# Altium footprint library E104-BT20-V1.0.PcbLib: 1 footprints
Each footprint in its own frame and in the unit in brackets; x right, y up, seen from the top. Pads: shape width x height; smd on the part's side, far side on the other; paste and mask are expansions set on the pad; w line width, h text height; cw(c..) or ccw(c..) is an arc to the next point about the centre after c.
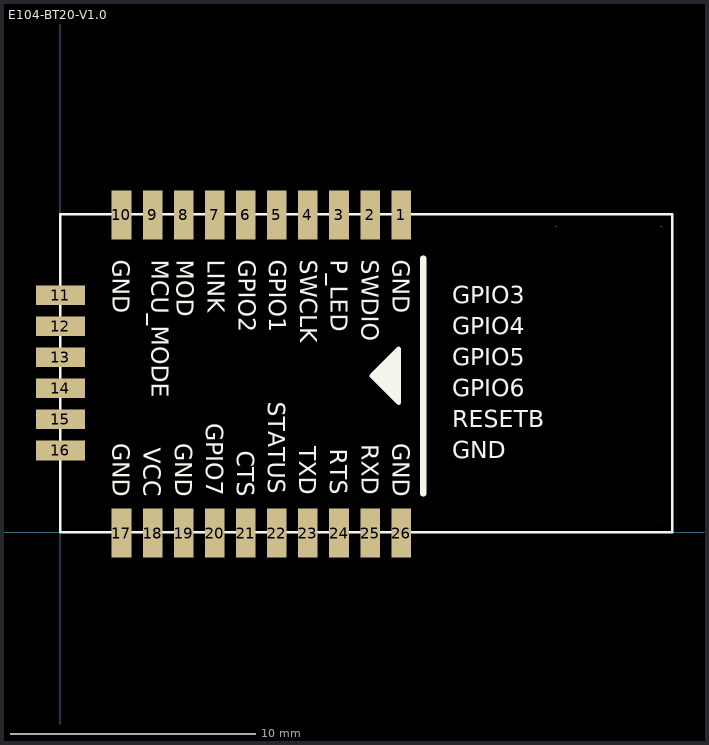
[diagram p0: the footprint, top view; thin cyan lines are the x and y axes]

## E104-BT20-V1.0 [mm]
pads (26):
  rect 0.8x2 smd: 1(13.927,12.975) 2(12.657,12.975) 3(11.387,12.975) 4(10.117,12.975) 5(8.847,12.975) 6(7.577,12.975) 7(6.307,12.975) 8(5.037,12.975) 9(3.77,12.975) 10(2.5,12.975) 17(2.5,-0.025) 18(3.77,-0.025) 19(5.037,-0.025) 20(6.307,-0.025) 21(7.577,-0.025) 22(8.847,-0.025) 23(10.117,-0.025) 24(11.387,-0.025) 25(12.657,-0.025) 26(13.927,-0.025)
  rect 2x0.8 smd: 11(0,9.7) 12(0,8.43) 13(0,7.16) 14(0,5.89) 15(0,4.62) 16(0,3.35)
Top Overlay:
  lines w0.1: 0,0 0,13 25,13 25,0 0,0
  lines w0.2: 13.727,7.2 13.327,6.8 ; 13.327,6.8 13.327,6.4 12.827,6.4 13.127,6.1 13.227,6.1 13.227,6.8 13.327,6.8 ; 13.327,6.8 13.427,6.9 13.427,6.1 13.527,6 13.527,5.8 13.527,7.1 13.627,7.2 13.627,5.7 13.827,5.5 ; 13.827,5.5 13.827,5.3 13.627,5.5 12.727,6.4 13.827,7.5 ; 13.827,5.5 13.827,7.5 ; 13.827,5.5 13.027,6.3 13.027,6.7 13.827,7.5
  lines w0.25: 14.827,1.6 14.827,11.2
  text "GND" at 16.013,3.03 h0.7
  text "RESETB" at 16.013,4.296 h0.7
  text "GPIO5" at 16.013,6.828 h0.7
  text "GPIO3" at 16.013,9.36 h0.7
  text "GPIO6" at 16.013,5.562 h0.7
  text "GPIO4" at 16.013,8.094 h0.7
  text "GND" at 2.147,3.64 h0.7
  text "GND" at 4.687,3.64 h0.7
  text "CTS" at 7.227,3.33 h0.7
  text "RTS" at 11.037,3.42 h0.7
  text "RXD" at 12.307,3.61 h0.7
  text "VCC" at 3.417,3.454 h0.7
  text "GPIO7" at 5.957,4.47 h0.7
  text "TXD" at 9.767,3.52 h0.7
  text "GND" at 13.577,3.64 h0.7
  text "STATUS" at 8.497,5.34 h0.7
  text "GND" at 2.147,11.142 h0.7
  text "MOD" at 4.763,11.142 h0.7
  text "GPIO2" at 7.281,11.142 h0.7
  text "GPIO1" at 8.541,11.142 h0.7
  text "SWDIO" at 12.318,11.142 h0.7
  text "LINK" at 6.022,11.142 h0.7
  text "SWCLK" at 9.8,11.142 h0.7
  text "GND" at 13.577,11.142 h0.7
  text "P_LED" at 11.059,11.142 h0.7
  text "MCU_MODE" at 3.737,11.142 h0.7
Mechanical 2:
  circle w0.006: c24.549,12.5 r0.003
  circle w0.006: c24.549,0.5 r0.003
  circle w0.006: c24.549,12.5 r0.003
  circle w0.006: c20.249,12.5 r0.003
